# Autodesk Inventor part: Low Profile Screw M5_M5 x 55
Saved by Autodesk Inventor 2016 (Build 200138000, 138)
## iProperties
Created: 2015-11
Part Number: Low Profile Screw M5_M5 x 55
Material: Generic
Document SubType Name: Modeling
Designer: John
Density: 1 g/cm^3
Appearance: Default
Author: John
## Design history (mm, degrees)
feature "SOLID1"
body "Solid1"
